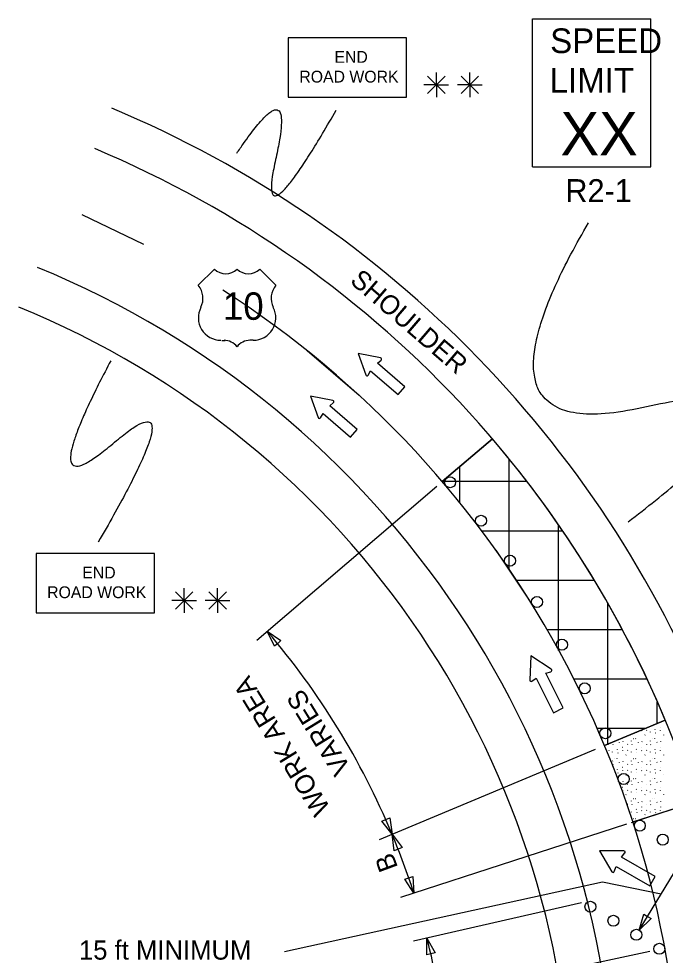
# Model space of a CAD drawing. Extents: x 16562 to 18475, y 6979 to 8243.
# Drawn here: x 16751.9 to 16987.7, y 7862.9 to 8204.4 of the extents above; entities that cross this region are included whole.
import ezdxf

# ---------------------------------------------------------------- set-up
doc = ezdxf.new("R2010")
doc.units = 0
for name, color, linetype in [('ALI_LEGAL_EX', 7, 'Continuous'), ('MT_SCRATCH_LEVEL_A', 7, 'Continuous'), ('MT_SCRATCH_LEVEL_E', 7, 'Continuous'), ('PAVT_EDGE_EX', 7, 'Continuous'), ('TRAFFIC_SIGNS_PR', 7, 'Continuous'), ('TYPICAL_EX', 7, 'Continuous'), ('TYPICAL_TEXT_DIMEN_PR', 7, 'Continuous')]:
    doc.layers.add(name, color=color, linetype=linetype)

msp = doc.modelspace()

# ---------------------------------------------------------------- linework, layer by layer
at = {"layer": 'ALI_LEGAL_EX'}
for points in [[(16797.55, 8122.12), (16774.98, 8132.88)], [(16876.06, 8067.02), (16857.11, 8083.33)], [(16939.89, 7989.85), (16925.99, 8010.63)]]:
    msp.add_lwpolyline(points, dxfattribs=at)
msp.add_arc((16629.65, 7799.18), 364, 0, 57.2958, dxfattribs=at)
at = {"layer": 'MT_SCRATCH_LEVEL_A'}
for p, q in [((16906.38, 8035.64), (16924.63, 8051.23)), ((16924.63, 8051.23), (16906.38, 8035.64)), ((16930.73, 8003.5), (16930.73, 8043.67)), ((16912.73, 8027.71), (16912.73, 8041.07)), ((16906.49, 8035.73), (16937.02, 8035.73)), ((16948.73, 7974.04), (16948.73, 8019.62)), ((16920.73, 8017.73), (16950.05, 8017.73)), ((16933.38, 7999.73), (16961.59, 7999.73)), ((16966.73, 7939.87), (16966.73, 7991.3)), ((16944.48, 7981.73), (16971.82, 7981.73)), ((16954.19, 7963.73), (16980.86, 7963.73)), ((16984.73, 7947.38), (16984.73, 7955.2)), ((16965.56, 7939.38), (16987.71, 7948.62)), ((16965.56, 7939.38), (16987.71, 7948.62)), ((16987.71, 7948.62), (16965.56, 7939.38)), ((16962.68, 7945.73), (16980.78, 7945.73)), ((16977.31, 7944.04), (16977.36, 7943.96)), ((16979.09, 7944.71), (16979.14, 7944.82)), ((16980.88, 7944.96), (16980.93, 7944.88)), ((16982.16, 7944.38), (16982.18, 7944.27)), ((16984.01, 7945.24), (16984.06, 7945.36)), ((16984.19, 7944.04), (16984.25, 7943.96)), ((16985.93, 7946.11), (16985.98, 7946.03)), ((16985.97, 7944.71), (16986.03, 7944.82)), ((16970.88, 7940.56), (16970.93, 7940.48)), ((16972.33, 7940.71), (16972.38, 7940.83)), ((16975.4, 7941.01), (16975.45, 7941.13)), ((16976.16, 7941.97), (16976.21, 7941.89)), ((16976.9, 7941.94), (16976.95, 7941.86)), ((16977.77, 7940.56), (16977.82, 7940.48)), ((16979.22, 7940.71), (16979.27, 7940.83)), ((16980.26, 7943.21), (16980.32, 7943.32)), ((16982.28, 7941.01), (16982.34, 7941.13)), ((16983.05, 7941.97), (16983.1, 7941.89)), ((16983.78, 7941.94), (16983.84, 7941.86)), ((16984.65, 7940.56), (16984.71, 7940.48)), ((16986.1, 7940.71), (16986.15, 7940.83)), ((16987.15, 7943.21), (16987.2, 7943.32)), ((16967.06, 7939.88), (16967.11, 7939.81)), ((16967.11, 7937.67), (16967.16, 7937.6)), ((16968.39, 7937.1), (16968.4, 7936.98)), ((16968.59, 7939.74), (16968.64, 7939.66)), ((16970.23, 7937.95), (16970.28, 7938.07)), ((16972.16, 7938.82), (16972.21, 7938.75)), ((16972.2, 7937.42), (16972.25, 7937.54)), ((16973.95, 7939.88), (16974, 7939.81)), ((16973.99, 7937.67), (16974.05, 7937.6)), ((16975.28, 7937.1), (16975.29, 7936.98)), ((16975.48, 7939.74), (16975.53, 7939.66)), ((16977.12, 7937.95), (16977.17, 7938.07)), ((16979.04, 7938.82), (16979.1, 7938.75)), ((16979.09, 7937.42), (16979.14, 7937.54)), ((16980.83, 7939.88), (16980.89, 7939.81)), ((16980.88, 7937.67), (16980.93, 7937.6)), ((16982.16, 7937.1), (16982.18, 7936.98)), ((16982.36, 7939.74), (16982.42, 7939.66)), ((16984.01, 7937.95), (16984.06, 7938.07)), ((16985.93, 7938.82), (16985.98, 7938.75)), ((16985.97, 7937.42), (16986.03, 7937.54)), ((16968.51, 7933.72), (16968.56, 7933.84)), ((16969.27, 7934.68), (16969.33, 7934.61)), ((16970.01, 7934.65), (16970.06, 7934.58)), ((16970.42, 7936.75), (16970.47, 7936.68)), ((16972.33, 7933.43), (16972.38, 7933.54)), ((16973.38, 7935.92), (16973.43, 7936.04)), ((16975.4, 7933.72), (16975.45, 7933.84)), ((16976.16, 7934.68), (16976.21, 7934.61)), ((16976.9, 7934.65), (16976.95, 7934.58)), ((16977.31, 7936.75), (16977.36, 7936.68)), ((16979.22, 7933.43), (16979.27, 7933.54)), ((16980.26, 7935.92), (16980.32, 7936.04)), ((16982.28, 7933.72), (16982.34, 7933.84)), ((16983.05, 7934.68), (16983.1, 7934.61)), ((16983.78, 7934.65), (16983.84, 7934.58)), ((16984.19, 7936.75), (16984.25, 7936.68)), ((16986.1, 7933.43), (16986.15, 7933.54)), ((16987.15, 7935.92), (16987.2, 7936.04)), ((16968.59, 7932.46), (16968.64, 7932.38)), ((16970.23, 7930.67), (16970.28, 7930.78)), ((16970.88, 7933.28), (16970.93, 7933.2)), ((16972.16, 7931.54), (16972.21, 7931.46)), ((16972.2, 7930.14), (16972.25, 7930.26)), ((16973.95, 7932.6), (16974, 7932.52)), ((16973.99, 7930.39), (16974.05, 7930.31)), ((16975.48, 7932.46), (16975.53, 7932.38)), ((16977.12, 7930.67), (16977.17, 7930.78)), ((16977.77, 7933.28), (16977.82, 7933.2)), ((16979.04, 7931.54), (16979.1, 7931.46)), ((16979.09, 7930.14), (16979.14, 7930.26)), ((16980.83, 7932.6), (16980.89, 7932.52)), ((16980.88, 7930.39), (16980.93, 7930.31)), ((16982.36, 7932.46), (16982.42, 7932.38)), ((16984.01, 7930.67), (16984.06, 7930.78)), ((16984.65, 7933.28), (16984.71, 7933.2)), ((16985.93, 7931.54), (16985.98, 7931.46)), ((16985.97, 7930.14), (16986.03, 7930.26)), ((16970.42, 7929.47), (16970.47, 7929.39)), ((16973.38, 7928.64), (16973.43, 7928.75)), ((16975.28, 7929.81), (16975.29, 7929.7)), ((16976.16, 7927.4), (16976.21, 7927.32)), ((16976.9, 7927.37), (16976.95, 7927.29)), ((16977.31, 7929.47), (16977.36, 7929.39)), ((16980.26, 7928.64), (16980.32, 7928.75)), ((16982.16, 7929.81), (16982.18, 7929.7)), ((16983.05, 7927.4), (16983.1, 7927.32)), ((16983.78, 7927.37), (16983.84, 7927.29)), ((16984.19, 7929.47), (16984.25, 7929.39)), ((16987.15, 7928.64), (16987.2, 7928.75)), ((16970.88, 7925.99), (16970.93, 7925.91)), ((16972.16, 7924.25), (16972.21, 7924.18)), ((16972.33, 7926.14), (16972.38, 7926.26)), ((16973.95, 7925.31), (16974, 7925.24)), ((16975.4, 7926.44), (16975.45, 7926.56)), ((16975.48, 7925.17), (16975.53, 7925.1)), ((16977.12, 7923.38), (16977.17, 7923.5)), ((16977.77, 7925.99), (16977.82, 7925.91)), ((16979.04, 7924.25), (16979.1, 7924.18)), ((16979.22, 7926.14), (16979.27, 7926.26)), ((16980.83, 7925.31), (16980.89, 7925.24)), ((16982.28, 7926.44), (16982.34, 7926.56)), ((16982.36, 7925.17), (16982.42, 7925.1)), ((16984.01, 7923.38), (16984.06, 7923.5)), ((16984.65, 7925.99), (16984.71, 7925.91)), ((16985.93, 7924.25), (16985.98, 7924.18)), ((16986.1, 7926.14), (16986.15, 7926.26)), ((16972.2, 7922.85), (16972.25, 7922.97)), ((16973.38, 7921.35), (16973.43, 7921.47)), ((16973.99, 7923.1), (16974.05, 7923.03)), ((16975.28, 7922.53), (16975.29, 7922.41)), ((16976.16, 7920.11), (16976.21, 7920.04)), ((16976.9, 7920.09), (16976.95, 7920.01)), ((16977.31, 7922.19), (16977.36, 7922.11)), ((16979.09, 7922.85), (16979.14, 7922.97)), ((16980.26, 7921.35), (16980.32, 7921.47)), ((16980.88, 7923.1), (16980.93, 7923.03)), ((16982.16, 7922.53), (16982.18, 7922.41)), ((16983.05, 7920.11), (16983.1, 7920.04)), ((16983.78, 7920.09), (16983.84, 7920.01)), ((16984.19, 7922.19), (16984.25, 7922.11)), ((16985.97, 7922.85), (16986.03, 7922.97)), ((16987.15, 7921.35), (16987.2, 7921.47)), ((16973.95, 7918.03), (16974, 7917.95)), ((16975.4, 7919.15), (16975.45, 7919.27)), ((16975.41, 7911.35), (16998.71, 7918.91)), ((16975.48, 7917.89), (16975.53, 7917.81)), ((16975.88, 7911.51), (16998.71, 7918.91)), ((16977.77, 7918.71), (16977.82, 7918.63)), ((16979.04, 7916.97), (16979.1, 7916.89)), ((16979.22, 7918.86), (16979.27, 7918.97)), ((16980.83, 7918.03), (16980.89, 7917.95)), ((16982.28, 7919.15), (16982.34, 7919.27)), ((16982.36, 7917.89), (16982.42, 7917.81)), ((16984.65, 7918.71), (16984.71, 7918.63)), ((16985.93, 7916.97), (16985.98, 7916.89)), ((16986.1, 7918.86), (16986.15, 7918.97)), ((16975.28, 7915.24), (16975.29, 7915.13)), ((16977.12, 7916.1), (16977.17, 7916.22)), ((16977.31, 7914.9), (16977.36, 7914.82)), ((16979.09, 7915.57), (16979.14, 7915.69)), ((16980.26, 7914.07), (16980.32, 7914.18)), ((16980.88, 7915.82), (16980.93, 7915.74)), ((16982.16, 7915.24), (16982.18, 7915.13)), ((16984.01, 7916.1), (16984.06, 7916.22)), ((16984.19, 7914.9), (16984.25, 7914.82)), ((16985.97, 7915.57), (16986.03, 7915.69)), ((16976.16, 7912.83), (16976.21, 7912.75)), ((16976.9, 7912.8), (16976.95, 7912.72))]:
    msp.add_line(p, q, dxfattribs=at)
msp.add_arc((16629.65, 7799.18), 388, 22.6538, 40.5126, dxfattribs=at)
at = {"layer": 'MT_SCRATCH_LEVEL_E'}
for p, q in [((16883.87, 8080.76), (16875.68, 8082.34)), ((16875.68, 8082.34), (16878.49, 8074.5)), ((16882.68, 8078.81), (16884.08, 8079.95)), ((16892.73, 8070.16), (16882.68, 8078.81)), ((16879.32, 8074.42), (16880.24, 8075.97)), ((16880.24, 8075.97), (16890.29, 8067.33)), ((16890.29, 8067.33), (16892.73, 8070.16)), ((16866.49, 8065.23), (16858.3, 8066.81)), ((16858.3, 8066.81), (16861.1, 8058.97)), ((16865.3, 8063.28), (16866.69, 8064.43)), ((16875.35, 8054.64), (16865.3, 8063.28)), ((16861.94, 8058.89), (16862.86, 8060.45)), ((16862.86, 8060.45), (16872.91, 8051.8)), ((16872.91, 8051.8), (16875.35, 8054.64))]:
    msp.add_line(p, q, dxfattribs=at)
for centre, start, end in [((16883.77, 8080.3), 309.3361, 79.073), ((16878.92, 8074.66), 199.7248, 329.2637), ((16866.39, 8064.78), 309.3361, 79.073), ((16861.54, 8059.14), 199.7248, 329.2637)]:
    msp.add_arc(centre, 0.463, start, end, dxfattribs=at)
at = {"layer": 'PAVT_EDGE_EX'}
for radius, start, end in [(404, 21.0961, 67.2667), (388, 17.5395, 67.2667), (340, 0, 67.6908), (324, 0, 67.8391)]:
    msp.add_arc((16629.65, 7799.18), radius, start, end, dxfattribs=at)
at = {"layer": 'TRAFFIC_SIGNS_PR'}
for p, q in [((16939.25, 8204.41), (16982.45, 8204.41)), ((16939.25, 8150.41), (16939.25, 8204.41)), ((16982.45, 8150.41), (16982.45, 8204.41)), ((16939.25, 8150.41), (16982.45, 8150.41))]:
    msp.add_line(p, q, dxfattribs=at)
for points in [[(16850.17, 8175.8), (16893.37, 8175.8), (16893.37, 8197.4), (16850.17, 8197.4)], [(16758.17, 7987.78), (16801.37, 7987.78), (16801.37, 8009.38), (16758.17, 8009.38)]]:
    msp.add_lwpolyline(points, close=True, dxfattribs=at)
for centre in [(16909.24, 8035.38), (16920.51, 8021.35), (16931.08, 8006.79), (16940.92, 7991.72), (16950.03, 7976.16), (16958.33, 7960.22), (16965.85, 7943.87), (16972.55, 7927.17), (16978.43, 7910.16), (16986.81, 7905.05), (16960.4, 7880.58), (16968.79, 7875.47), (16977.17, 7870.36), (16985.56, 7865.25), (16985.56, 7865.25)]:
    msp.add_circle(centre, 2, dxfattribs=at)
at = {"layer": 'TYPICAL_EX'}
for p, q in [((16817.36, 8107.2), (16823.25, 8113.1)), ((16845.65, 8107.2), (16839.76, 8113.1)), ((16825.95, 8087.13), (16827.13, 8087.13)), ((16837.41, 8087.14), (16836.23, 8087.14))]:
    msp.add_line(p, q, dxfattribs=at)
for centre, radius, start, end in [((16827.38, 8117.39), 5.96, 226.1404, 313.8596), ((16835.63, 8117.39), 5.96, 226.1404, 313.8596), ((16811.77, 8102.48), 7.31, 333.0977, 40.1936), ((16851.24, 8102.48), 7.31, 139.8064, 206.9023), ((16825.62, 8095.38), 8.24, 152.6698, 269.9013), ((16837.39, 8095.38), 8.24, 270.0987, 27.3302), ((16826.79, 8081.23), 5.91, 37.1038, 90.1385), ((16836.21, 8081.23), 5.91, 89.8615, 142.8962)]:
    msp.add_arc(centre, radius, start, end, dxfattribs=at)
at = {"layer": 'TYPICAL_TEXT_DIMEN_PR'}
for p, q in [((16901.02, 8183.49), (16907.39, 8177.11)), ((16907.39, 8183.49), (16901.02, 8177.11)), ((16904.21, 8180.3), (16904.21, 8184.76)), ((16919.6, 8183.49), (16913.22, 8177.11)), ((16913.23, 8183.49), (16919.6, 8177.11)), ((16916.41, 8180.3), (16916.41, 8184.76)), ((16904.21, 8180.3), (16899.67, 8180.3)), ((16904.21, 8180.3), (16907.39, 8180.3)), ((16904.21, 8180.3), (16908.68, 8180.3)), ((16904.21, 8180.3), (16904.21, 8175.8)), ((16916.41, 8180.3), (16911.88, 8180.3)), ((16916.41, 8180.3), (16919.6, 8180.3)), ((16916.41, 8180.3), (16920.89, 8180.3)), ((16916.41, 8180.3), (16916.41, 8175.8)), ((16838.72, 7977.82), (16904.36, 8033.91)), ((16809.03, 7995.46), (16815.4, 7989.09)), ((16815.4, 7995.46), (16809.03, 7989.09)), ((16812.21, 7992.27), (16812.21, 7996.73)), ((16827.61, 7995.46), (16821.23, 7989.09)), ((16821.24, 7995.46), (16827.61, 7989.09)), ((16824.42, 7992.27), (16824.42, 7996.73)), ((16812.21, 7992.27), (16807.68, 7992.27)), ((16812.21, 7992.27), (16815.4, 7992.27)), ((16812.21, 7992.27), (16816.69, 7992.27)), ((16812.21, 7992.27), (16812.21, 7987.77)), ((16824.42, 7992.27), (16819.89, 7992.27)), ((16824.42, 7992.27), (16827.61, 7992.27)), ((16824.42, 7992.27), (16828.9, 7992.27)), ((16824.42, 7992.27), (16824.42, 7987.77)), ((16845.14, 7975.6), (16842.52, 7981.07)), ((16842.52, 7981.07), (16847.53, 7977.64)), ((16846.33, 7976.62), (16845.14, 7975.6)), ((16847.53, 7977.64), (16846.33, 7976.62)), ((16938.73, 7972.12), (16938.25, 7963.25)), ((16946.14, 7967.18), (16938.73, 7972.12)), ((16944.16, 7965.76), (16946.01, 7966.3)), ((16950.47, 7953.1), (16944.16, 7965.76)), ((16939.04, 7962.83), (16940.59, 7963.98)), ((16940.59, 7963.98), (16946.9, 7951.32)), ((16946.9, 7951.32), (16950.47, 7953.1)), ((16883.43, 7905.1), (16962.31, 7938.02)), ((16885.79, 7912.44), (16887.24, 7913.04)), ((16887.24, 7913.04), (16888.05, 7907.03)), ((16884.34, 7911.83), (16885.79, 7912.44)), ((16888.05, 7907.03), (16884.34, 7911.83)), ((16891.23, 7884.04), (16973.68, 7910.79)), ((16888.85, 7901.01), (16888.05, 7907.03)), ((16888.05, 7907.03), (16891.75, 7902.22)), ((16890.3, 7901.62), (16888.85, 7901.01)), ((16891.75, 7902.22), (16890.3, 7901.62)), ((16972.64, 7900.99), (16963.74, 7901.02)), ((16963.74, 7901.02), (16968.24, 7893.36)), ((16971.77, 7898.71), (16973.01, 7900.19)), ((16984.02, 7891.65), (16971.77, 7898.71)), ((16978.21, 7872.07), (16994.16, 7898.23)), ((16969.12, 7893.44), (16969.78, 7895.25)), ((16969.78, 7895.25), (16982.03, 7888.19)), ((16964.78, 7889.59), (16848.85, 7864.21)), ((16892.68, 7890.68), (16894.17, 7891.16)), ((16895.98, 7885.59), (16892.68, 7890.68)), ((16894.17, 7891.16), (16895.67, 7891.65)), ((16895.67, 7891.65), (16895.98, 7885.59)), ((16986.19, 7885.15), (16964.78, 7889.59)), ((16982.03, 7888.19), (16984.02, 7891.65)), ((16957.1, 7882.05), (16895.9, 7867.99)), ((16978.21, 7872.07), (16979.92, 7877.89)), ((16982.61, 7876.26), (16978.21, 7872.07)), ((16979.92, 7877.89), (16981.26, 7877.07)), ((16981.26, 7877.07), (16982.61, 7876.26)), ((16900.72, 7863.04), (16900.78, 7869.11)), ((16900.78, 7869.11), (16903.76, 7863.83)), ((16872.98, 7841.11), (16982.07, 7864.4)), ((16902.24, 7863.44), (16900.72, 7863.04)), ((16903.76, 7863.83), (16902.24, 7863.44))]:
    msp.add_line(p, q, dxfattribs=at)
for centre, radius, start, end in [((16629.65, 7799.18), 280, 22.6539, 40.5126), ((16945.85, 7966.78), 0.494, 286.5439, 56.2808), ((16938.75, 7963.23), 0.494, 176.9326, 306.4715), ((16629.65, 7799.18), 280, 17.974, 22.6539), ((16972.63, 7900.5), 0.494, 320.0605, 89.7974), ((16968.66, 7893.62), 0.494, 210.4492, 339.9881), ((16629.65, 7799.18), 280, 10.0461, 14.4629)]:
    msp.add_arc(centre, radius, start, end, dxfattribs=at)
for points in [[(16831.41, 8155.37), (16853.44, 8187.97), (16837.89, 8119.13), (16867.69, 8171.08)], [(16974.12, 8020.9), (17049.68, 8078.69), (16911.07, 8046.86), (16959.72, 8130.04)], [(16785.42, 8079.66), (16755.62, 8023.33), (16817.16, 8075.93), (16780.88, 8013.58)]]:
    msp.add_open_spline(points, degree=2, dxfattribs=at)

# ---------------------------------------------------------------- texts
at = {"layer": 'TRAFFIC_SIGNS_PR'}
for s, height, p in [('SPEED', 9, (16945.73, 8191.88)), ('END', 4.31, (16867.04, 8188.33)), ('LIMIT', 9, (16945.55, 8177.48)), ('ROAD WORK', 4.31, (16854.23, 8181.14)), ('XX', 15.785, (16949.5, 8154.64)), ('R2-1', 8.37, (16951.26, 8137.54)), ('END', 4.31, (16775.05, 8000.3)), ('ROAD WORK', 4.31, (16762.23, 7993.12))]:
    msp.add_text(s, height=height, dxfattribs=at).set_placement(p)
at = {"layer": 'TYPICAL_EX'}
msp.add_text('10', height=10, dxfattribs=at).set_placement((16826.35, 8094.62))
at = {"layer": 'TYPICAL_TEXT_DIMEN_PR'}
for s, rotation, p in [('SHOULDER', 319.2839, (16872.35, 8108.31)), ('WORK AREA', 121.5829, (16865.78, 7916.51)), ('VARIES', 121.5829, (16873.18, 7931.21)), ('B', 110.315, (16890.29, 7894.92))]:
    msp.add_text(s, height=7, rotation=rotation, dxfattribs=at).set_placement(p)
msp.add_text('15 ft MINIMUM', height=7, dxfattribs=at).set_placement((16773.82, 7861.31))

doc.saveas('drawing.dxf')
